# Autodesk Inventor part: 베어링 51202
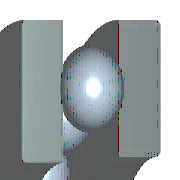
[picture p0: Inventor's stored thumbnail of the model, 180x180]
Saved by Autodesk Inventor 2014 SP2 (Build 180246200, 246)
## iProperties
Created: 2012-02
Part Number: 베어링 51202
Material: 강철, 연강
Description: 롤링 베어링 - 플랫 뒷면이 있는 스러스트 볼 베어링
Document SubType Name: Modeling
Standard: KS B 2022
Designer: mduedu
Standards Organization: KS
Language: ko-KR
Size Designation: 51202 - 15 x 32 x 12
Categories: <MemberInstance><Categories><Category DisplayName="샤프트 부품" InternalName="7f7aeb1f-a693-4053-b835-cee3144e0d98" Mnemonic="SHFT"><Category DisplayName="베어링" Inter
Density: 1 g/cm^3
Appearance: 진녹색
IsCustomPart: 1
Author: mduedu
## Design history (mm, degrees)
sketch "스케치1" dims "d3" = 5.28 (= 0.44 x KB)
  geometry: L1 (6, 9.61)-(6, 14.89); L2 (8.64, 12.25)-(3.36, 12.25); L3 (3.6, 16)-(0, 16); L4 (3.6, 7.5)-(0, 7.5); L5 (8.4, 13.35)-(8.4, 16); L6 (8.4, 16)-(12, 16); L7 (12, 16)-(12, 8.5); L8 (12, 8.5)-(8.4, 8.5); L9 (8.4, 8.5)-(8.4, 11.15); L10 (3.6, 16)-(3.6, 13.35); L11 (3.6, 11.15)-(3.6, 7.5); L12 (-1.8, 0)-(10.8, 0) reference; L13 (0, -0.022)-(0, 5.522) reference; 1 further point
  constraints: 22 end point, 5 perpendicular, 2 equal length, 2 midpoint, 2 parallel, 2 point on line, 1 collinear, 10 other
  dimensions: "d8" = 4.8 diameter of L11 L1 (= 0.4 x KB); "d11" = 15 diameter of L4 L12 (= WD); "d12" = 17 diameter of L8 L12 (= KAD1); "d13" = 32 diameter of L3 L12 (= KID1); "d14" = 32 diameter of L6 L12 (= BD); "d15" = 24.5 diameter of point (6, 12.25) L12 (= 0.5 x KID1 + 0.5 x KAD1); "d16" = 6 distance from line of point (6, 12.25) L13 (= 0.5 x KB); "d18" = 12 distance between parallel lines of L7 L13 (= KB)
revolve "본체" stored, may be unused: angle "d9" = 90 deg
revolve "볼" stored, may be unused: angle "d10" = 90 deg
pattern_circular "IDS_ARRAYBALL[SIMPL:T]" dims angle "d2" = 360 deg
body "Solid1"
fillet "모깎기1" dims "d4" = 0.6 (= KRS)
fillet "모깎기2" dims "d5" = 0.6 (= KRS)
other parameters: "WD" = 15 [user parameter; used in 2 equation terms], "KAD1" = 17 [user parameter; used in 3 equation terms], "KID1" = 32 [user parameter; used in 3 equation terms], "BD" = 32 [user parameter; used in 2 equation terms], "KB" = 12 [user parameter; used in 6 equation terms], "KRS" = 0.6 [user parameter; used in 2 equation terms], "d0" = 2.4 (= 0.2 x KB), "d6" = 0, "d7" = 0, "d19" = 0, "d41" = 0, "d42" = 0, "WR" = 7.5 (= 0.5 x WD) [user parameter], "BC" = 1.65e+07 [user parameter], "BBA" = 90 deg [user parameter], "BC0" = 2.7e+07 [user parameter], "BR" = 16 (= 0.5 x BD) [user parameter]
